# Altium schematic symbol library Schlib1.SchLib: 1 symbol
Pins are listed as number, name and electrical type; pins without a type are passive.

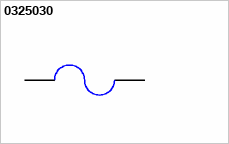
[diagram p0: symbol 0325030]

## 0325030
designator F?
Fuse, 30 A, 250 VAC, 125 VDC, TH; Manufacturer: LittleFuse
footprint 0325030
pins: 1, 2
